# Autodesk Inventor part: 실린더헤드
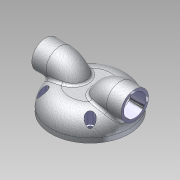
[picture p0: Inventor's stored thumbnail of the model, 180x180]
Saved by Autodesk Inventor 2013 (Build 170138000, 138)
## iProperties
Manager: KYOUNG IL JANG
Company: 한국ATC센터
Created: 2012-10
Part Number: 실린더헤드
Document SubType Name: Modeling
Density: 1 g/cm^3
Checked By: KYOUNG IL JANG
Vendor: CBT Solutions
Designer: KYOUNG IL JANG
Material: 일반
Author: KYOUNG IL JANG
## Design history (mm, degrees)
sketch "스케치1"
  geometry: C1 r 42.5 at (0, 0); 1 further point
  constraints: 1 centre point, 1 coincident
  dimensions: "d0" = 85 diameter of C1
extrude "돌출1" new body sketch "스케치1" distance "d1" = 25; taper "d2" = 0 deg
fillet "모깎기1" dims "d3" = 20
sketch "스케치2"
  geometry: C1 r 30 at (0, 0); 1 further point
  constraints: 1 centre point, 1 coincident
  dimensions: "d4" = 60 diameter of C1
extrude "돌출2" join sketch "스케치2" distance "d5" = 5; taper "d6" = 0 deg
sketch "스케치3"
  geometry: L1 (-42.5, 0)-(42.5, 0) reference; L2 (-48.5, 30)-(-33, 30); L3 (-17.545, 18.141)-(-12.684, 0); A1 r 16 centre (-33, 14) between (-17.545, 18.141) and (-33, 30); 1 further point
  constraints: 4 end point, 2 point on circle, 2 tangent, 1 centre point, 1 parallel, 1 point on line
  dimensions: "d7" = 16 radius of A1; "d8" = 6 horizontal distance of L2.start L1.start; "d9" = 30 distance between parallel lines of L2 L1; "d11" = 105 deg angle of L3 L1; "d36" = 15.5 distance of L2.start L2.end
node "작업 평면1"
sketch "스케치4"
  geometry: C1 r 15 at (0, 0); C2 r 12 at (0, 0); 2 further points
  constraints: 2 centre point, 2 coincident
  dimensions: "d12" = 30 diameter of C1; "d13" = 3 radial gap between concentric circles of C2 C1
feature "스윕1" dims "d14" = 0
feature "스윕2" dims "d15" = 0
sketch "스케치5"
  geometry: L1 (30, -5)-(-30, -5) reference; L2 (0, -5)-(0, 10); L3 (0, 10)-(-10, 10); A1 r 15 centre (-10, -5) between (-10, 10) and (-25, -5); 1 further point
  constraints: 4 end point, 2 perpendicular, 2 point on circle, 1 centre point, 1 midpoint, 1 point on line, 1 tangent
  dimensions: "d16" = 15 distance of L2.start L2.end; "d17" = 15 radius of A1; "d18" = 5 distance of L1.end A1.end
revolve "회전1" sketch "스케치5" stored, may be unused: angle "d19" = 90 deg
fillet "모깎기2" dims "d20" = 3
node "작업 평면2"
sketch "스케치6"
  geometry: L1 (0, 0)-(36.25, 0); C1 r 4.75 at (25.633, 25.633); C2 r 2.75 at (25.633, 25.633); A1 r 36.25 centre (0, 0) between (25.633, 25.633) and (36.25, 0); 1 further point
  constraints: 3 centre point, 2 coincident, 2 end point, 2 point on circle, 1 horizontal
  dimensions: "d22" = 72.5 diameter of A1; "d23" = 5.5 diameter of C2; "d24" = 9.5 diameter of C1; "d37" = 45 deg dimension on point (0, 0) C1.centre L1.end
extrude "돌출3" cut sketch "스케치6" stored distance "d25" = 5; taper "d26" = 0 deg
extrude "돌출4" cut sketch "스케치6" stored distance "d27" = 5; taper "d28" = 0 deg
chamfer "모따기1" distance "d33" = 1; stored, may be unused: second distance "d34" = 2, angle "d35" = 45 deg
node "솔리드1"
mirror "대칭1"
pattern_circular "원형 패턴1" dims angle "d30" = 360 deg
